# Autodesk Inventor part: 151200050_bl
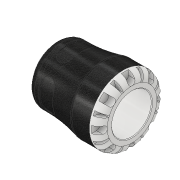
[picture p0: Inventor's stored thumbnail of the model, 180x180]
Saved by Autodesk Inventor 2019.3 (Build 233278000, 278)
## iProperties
Created: 2016-12
Part Number: 151200050_bl
Material: PVC-Piping
Description: PLASSON G-PLASS END CAP 50
Document SubType Name: Modeling
Designer: KIM
Mass: 57.8335 g
Surface Area: 121.129 cm^2
Volume: 41.3096 cm^3
Density: 1.4 g/cm^3
Appearance: Black Cast
Author: KIM
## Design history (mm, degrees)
derived "151200.ipt"
feature "Solid1::151200.ipt" dims "ScaleForDerivedMember" = 10
tag "TaggingFeature1"
body "Solid1"
other parameters: "d0" = 106 [user parameter], "d1" = 34.44 [user parameter], "d3" = 62.5 [user parameter], "d4" = 85 [user parameter], "d6" = 82 [user parameter], "d7" = 90.2 [user parameter], "d8" = 72.25 [user parameter], "d13" = 9 [user parameter], "d14" = 9 [user parameter], "d15" = 0 [user parameter], "d17" = 360 deg [user parameter], "d19" = 8 deg [user parameter], "d20" = 1 [user parameter], "d21" = 1 [user parameter], "d22" = 8 deg [user parameter], "d24" = 0 [user parameter], "d26" = 360 deg [user parameter], "d32" = 8.5 [user parameter], "d33" = 8.5 [user parameter], "d34" = 11 [user parameter], "d35" = 17.5 [user parameter], "d36" = 17.64 [user parameter], "d37" = 0 [user parameter], "d42" = 360 deg [user parameter], "d45" = 14.875 [user parameter], "d46" = 1 [user parameter], "d48" = 0 [user parameter], "d49" = 0.85 [user parameter], "E_" = 85 [user parameter], "H_" = 106 [user parameter], "l_" = 82 [user parameter], "d9" = 11.25 [user parameter], "d11" = 85 [user parameter], "d12" = 62.5 [user parameter]
